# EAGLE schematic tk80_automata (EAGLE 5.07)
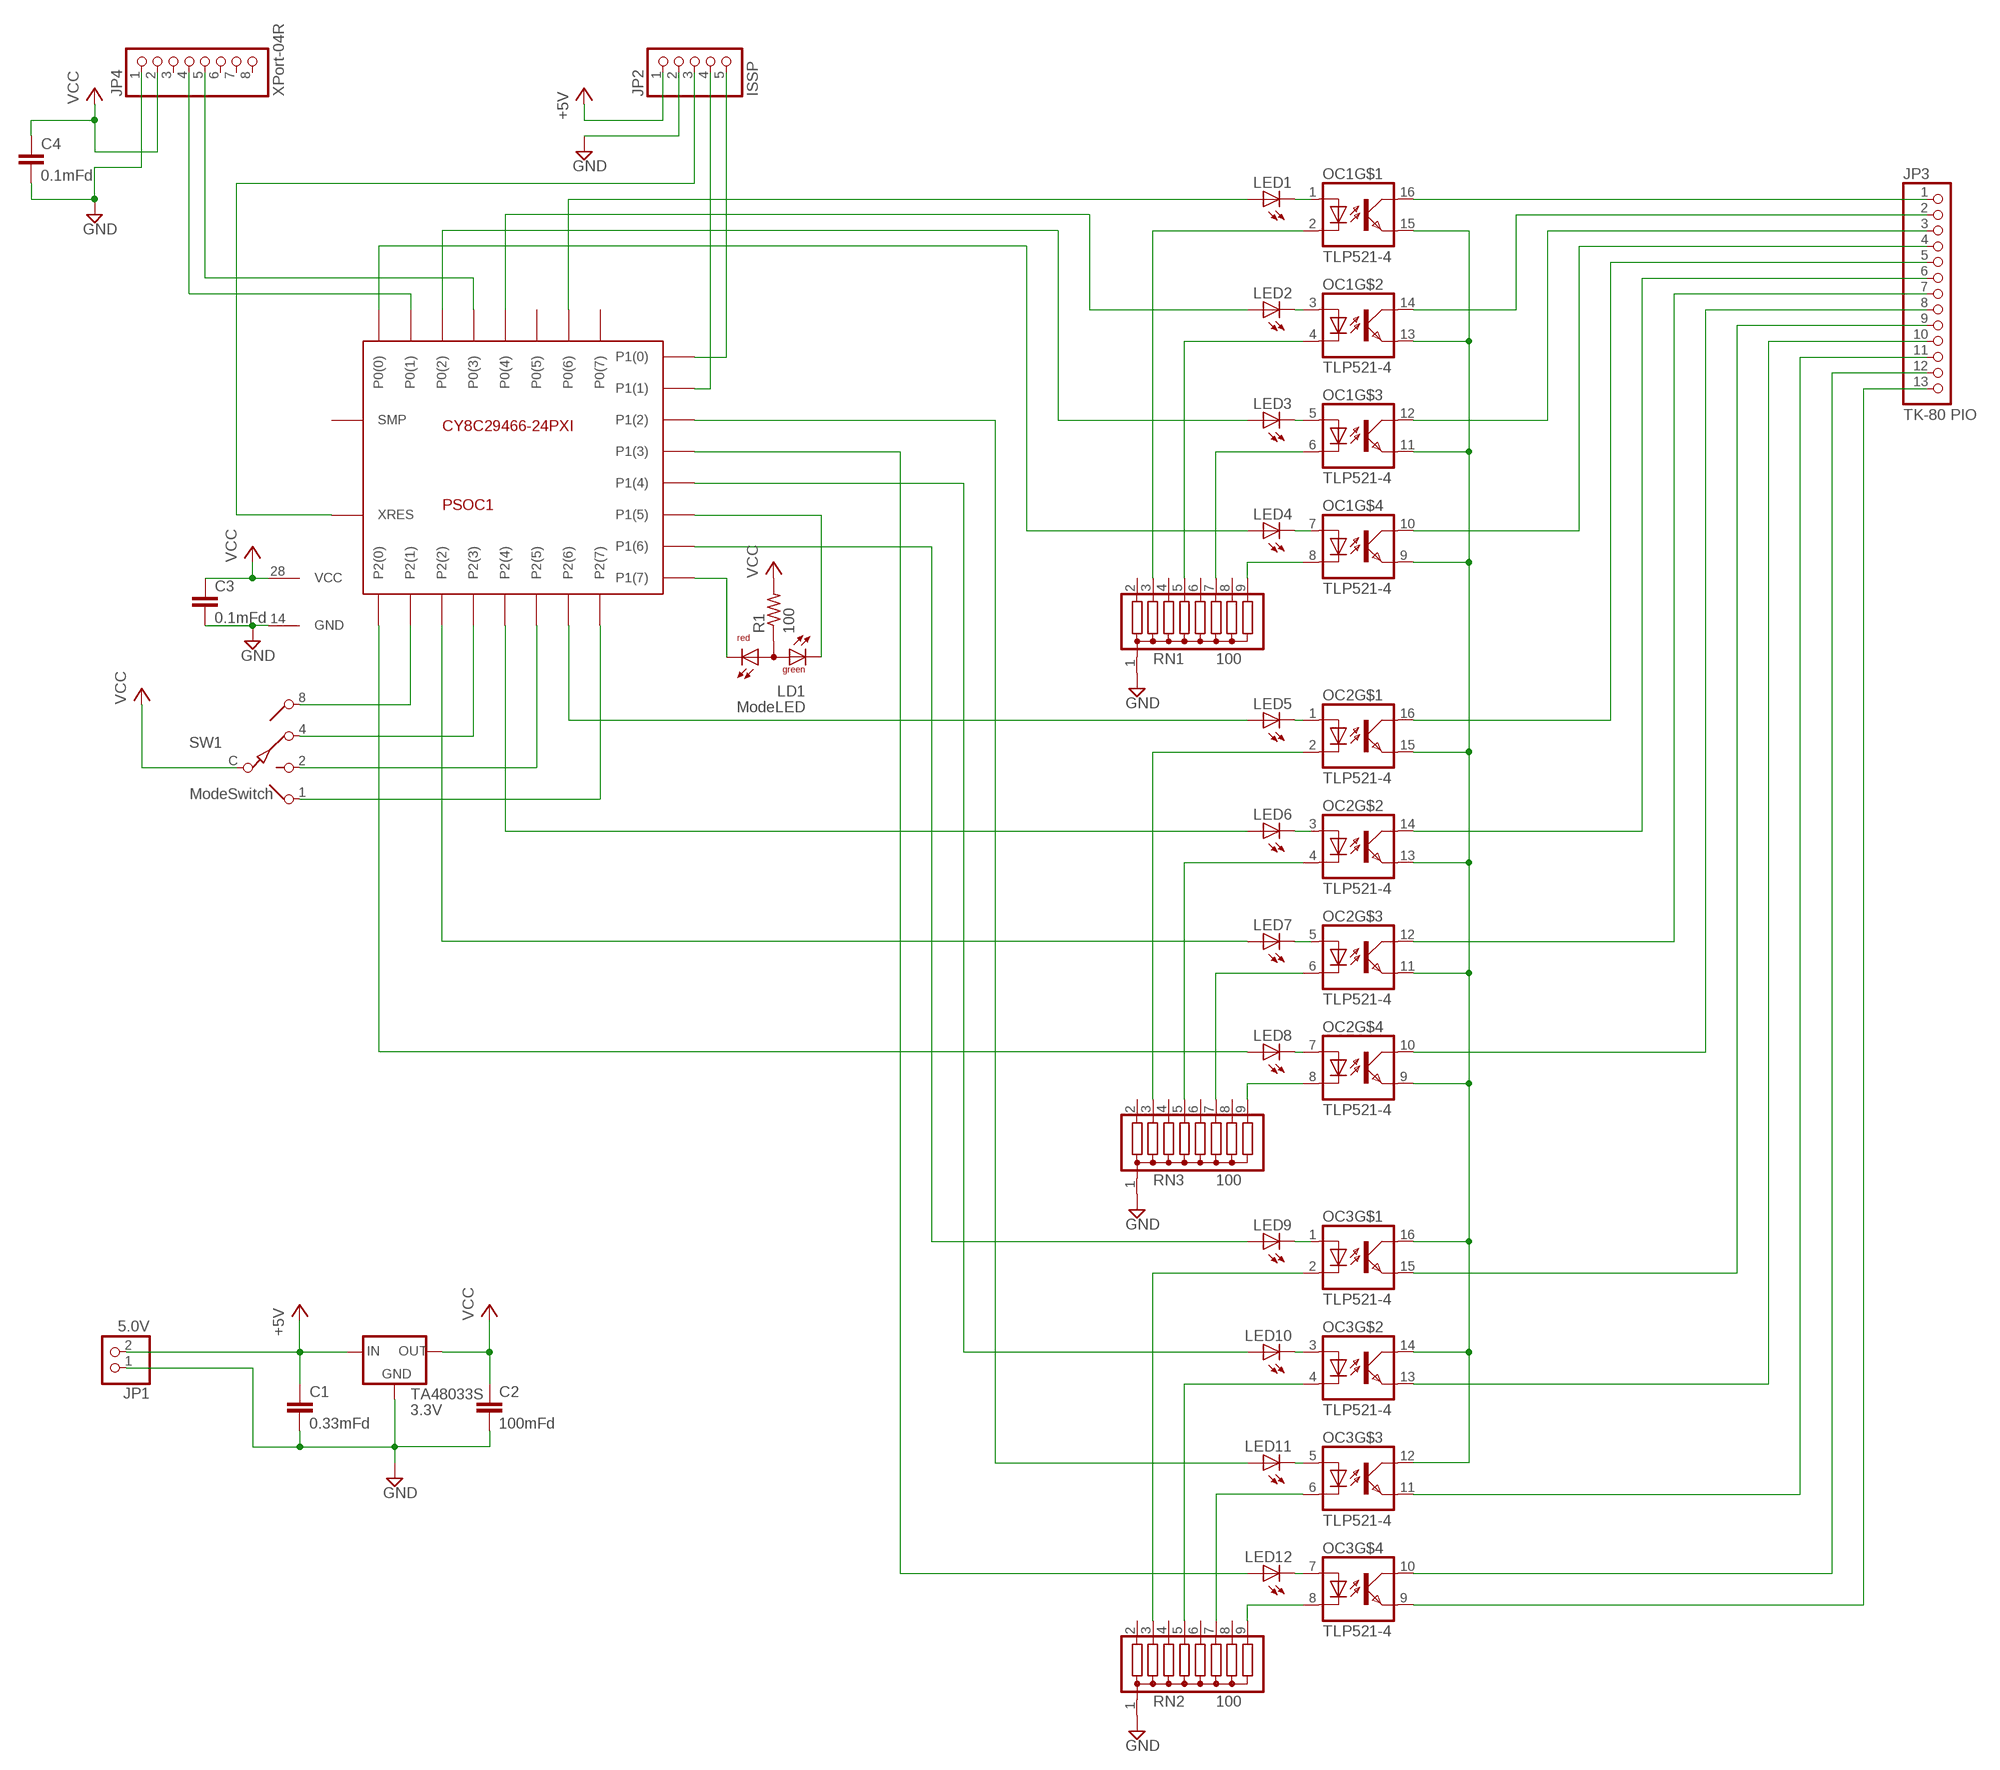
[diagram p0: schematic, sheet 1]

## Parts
C1  0.33mFd  C-EU025-025X050  [C025-025X050]
C2  100mFd  C-EU025-025X050  [C025-025X050]
C3  0.1mFd  C-EU025-025X050  [C025-025X050]
C4  0.1mFd  C-EU025-025X050  [C025-025X050]
JP1  5.0V  PINHD-1X2/90  [1X02/90]
JP2  ISSP  PINHD-1X5/90  [1X05/90]
JP3  TK-80 PIO  PINHD-1X13  [1X13]
JP4  XPort-04R  PINHD-1X8  [1X08]
LD1  ModeLED  DUOLED-RG-A  [DUOLED-A-5MM]
LED1  LED3MM  [LED3MM]
LED2  LED3MM  [LED3MM]
LED3  LED3MM  [LED3MM]
LED4  LED3MM  [LED3MM]
LED5  LED3MM  [LED3MM]
LED6  LED3MM  [LED3MM]
LED7  LED3MM  [LED3MM]
LED8  LED3MM  [LED3MM]
LED9  LED3MM  [LED3MM]
LED10  LED3MM  [LED3MM]
LED11  LED3MM  [LED3MM]
LED12  LED3MM  [LED3MM]
OC1  TLP521-4  [DIP16]
OC2  TLP521-4  [DIP16]
OC3  TLP521-4  [DIP16]
PSOC1  CY8C29466-24PXI  [PDIP28]
R1  100  R-US_0204/2V  [0204V]
RN1  100  G08R  [SIL9]
RN2  100  G08R  [SIL9]
RN3  100  G08R  [SIL9]
SW1  ModeSwitch  SW-C16  [SW-C16]
TA48033S  3.3V  78XXL  [78XXL]

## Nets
+5V: C1.1 JP1.2 JP2.1 TA48033S.IN
GND: C1.2 C2.2 C3.2 C4.2 JP1.1 JP2.2 JP4.1 PSOC1.14(GND) RN1.1 RN2.1 RN3.1 TA48033S.GND
N$1: OC1.2(C) RN1.3
N$2: OC1.4(C) RN1.5
N$3: OC1.6(C) RN1.7
N$4: OC1.8(C) RN1.9
N$5: OC2.8(C) RN3.9
N$6: OC2.6(C) RN3.7
N$7: OC2.4(C) RN3.5
N$8: OC2.2(C) RN3.3
N$9: OC3.8(C) RN2.9
N$10: OC3.6(C) RN2.7
N$11: OC3.4(C) RN2.5
N$12: OC3.2(C) RN2.3
N$13: JP3.1 OC1.16(COL)
N$14: OC1.9(EMIT) OC1.11(EMIT) OC1.13(EMIT) OC1.15(EMIT) OC2.9(EMIT) OC2.11(EMIT) OC2.13(EMIT) OC2.15(EMIT) OC3.12(COL) OC3.14(COL) OC3.16(COL)
N$15: JP3.2 OC1.14(COL)
N$16: JP3.3 OC1.12(COL)
N$17: JP3.4 OC1.10(COL)
N$18: JP3.5 OC2.16(COL)
N$19: JP3.6 OC2.14(COL)
N$20: JP3.7 OC2.12(COL)
N$21: JP3.8 OC2.10(COL)
N$22: JP3.9 OC3.15(EMIT)
N$23: JP3.10 OC3.13(EMIT)
N$24: JP3.11 OC3.11(EMIT)
N$25: JP3.12 OC3.10(COL)
N$26: JP3.13 OC3.9(EMIT)
N$27: LED1.A PSOC1.27(P0(6))
N$28: LED2.A PSOC1.26(P0(4))
N$29: LED3.A PSOC1.25(P0(2))
N$30: LED4.A PSOC1.24(P0(0))
N$31: LED5.A PSOC1.23(P2(6))
N$32: LED6.A PSOC1.22(P2(4))
N$33: LED7.A PSOC1.21(P2(2))
N$34: LED8.A PSOC1.20(P2(0))
N$35: JP4.4 PSOC1.4(P0(1))
N$36: LED9.A PSOC1.18(P1(6))
N$37: LED10.A PSOC1.17(P1(4))
N$38: LED11.A PSOC1.16(P1(2))
N$39: LED12.A PSOC1.12(P1(3))
N$40: JP2.5 PSOC1.15(P1(0))
N$41: JP2.4 PSOC1.13(P1(1))
N$42: JP2.3 PSOC1.19(XRES)
N$43: PSOC1.7(P2(3)) SW1.4
N$44: LD1.A R1.1
N$46: LED1.K(C) OC1.1(A)
N$47: LD1.CR PSOC1.10(P1(7))
N$48: PSOC1.8(P2(1)) SW1.8
N$49: LD1.CX(CG) PSOC1.11(P1(5))
N$50: PSOC1.6(P2(5)) SW1.2
N$51: PSOC1.5(P2(7)) SW1.1
N$52: LED2.K(C) OC1.3(A)
N$53: JP4.5 PSOC1.3(P0(3))
N$54: LED3.K(C) OC1.5(A)
N$55: LED4.K(C) OC1.7(A)
N$56: LED5.K(C) OC2.1(A)
N$57: LED6.K(C) OC2.3(A)
N$58: LED7.K(C) OC2.5(A)
N$59: LED8.K(C) OC2.7(A)
N$60: LED9.K(C) OC3.1(A)
N$61: LED10.K(C) OC3.3(A)
N$62: LED11.K(C) OC3.5(A)
N$63: LED12.K(C) OC3.7(A)
VCC: C2.1 C3.1 C4.1 JP4.2 PSOC1.28(VCC) R1.2 SW1.C TA48033S.OUT
Unconnected: JP4.3 JP4.6 JP4.7 JP4.8 PSOC1.1(P0(7)) PSOC1.2(P0(5)) PSOC1.9(SMP) RN1.2 RN1.4 RN1.6 RN1.8 RN2.2 RN2.4 RN2.6 RN2.8 RN3.2 RN3.4 RN3.6 RN3.8

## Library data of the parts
C1-C4 = rcl:C-EU: CAPACITOR, European symbol
JP1 = pinhead:PINHD-1X2: PIN HEADER
JP2 = pinhead:PINHD-1X5: PIN HEADER
JP3 = pinhead:PINHD-1X13: PIN HEADER
JP4 = pinhead:PINHD-1X8: PIN HEADER
LD1 = led:DUOLED-RG-A: DUO LED 2 colors (red/green), 5 mm, round, common Anode www.ligitek.com or other producers.
LED1-LED12 = led:LED: LED
OC1-OC3 = mizunon:TLP521-4: Opt Coupler OptCounpler TLP521-4
PSOC1 = mizunon:CY8C29466-24PXI: Cypress PSoC 29466 Cypress PSoC 29466
R1 = rcl:R-US_: RESISTOR, American symbol
RN1-RN3 = resistor-sil:G08R: SIL RESISTOR
SW1 = special:SW-C16: SWITCH 16-step rotary switch
TA48033S = v-reg:78XXL: VOLTAGE REGULATOR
